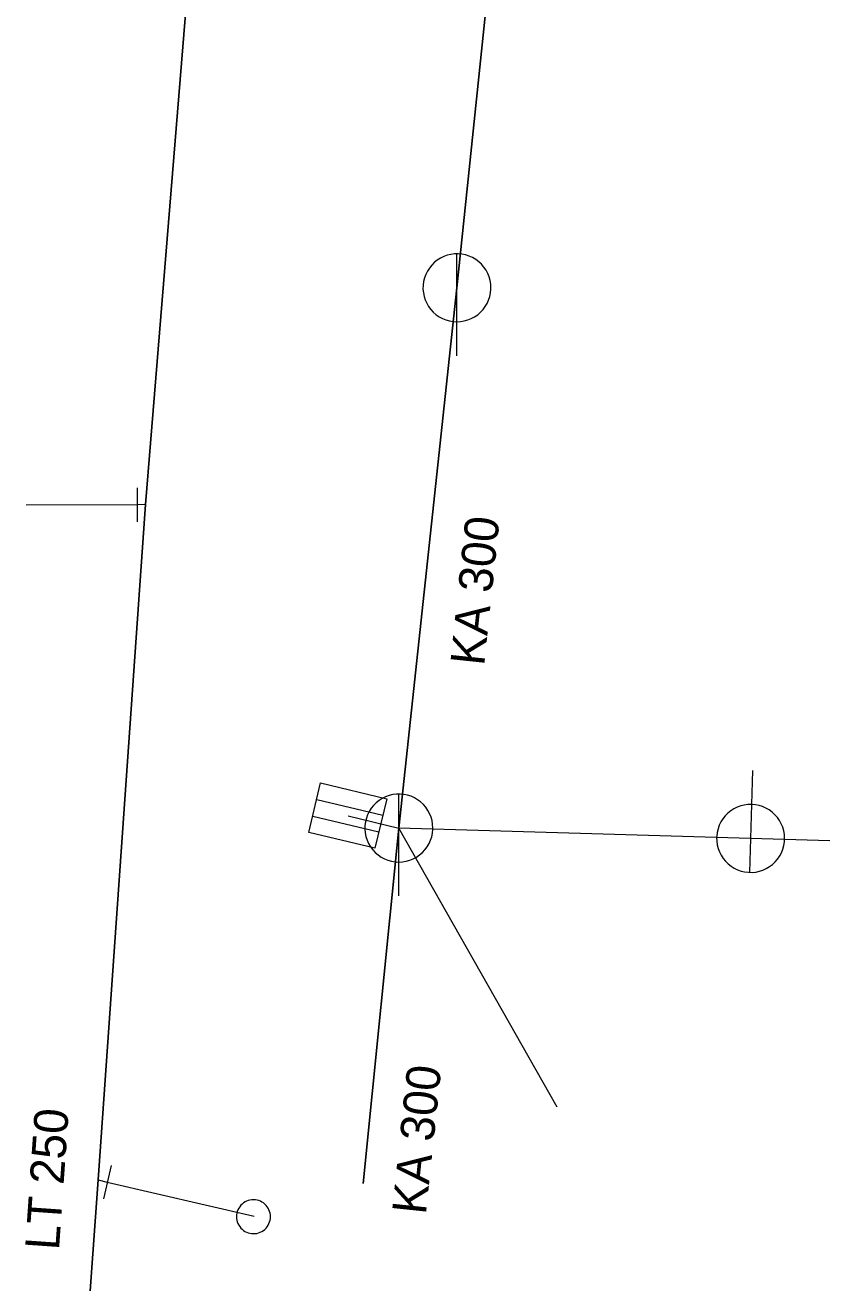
# Model space of a CAD drawing. Extents: x -783064 to -782702, y -1007904 to -1007145.
# Drawn here: x -782834.13 to -782810.46, y -1007875.4 to -1007838.15 of the extents above; entities that cross this region are included whole.
import ezdxf

# ---------------------------------------------------------------- set-up
doc = ezdxf.new("R2010")
doc.units = 0
doc.header["$LTSCALE"] = 0.4
for name, color, linetype, lineweight in [('1', 7, 'Continuous', 13), ('11', 7, 'Continuous', 13), ('13', 7, 'Continuous', 13), ('14', 7, 'Continuous', 13), ('17', 7, 'Continuous', 25), ('22', 7, 'Continuous', 13), ('23', 7, 'Continuous', 13), ('34', 7, 'Continuous', 13)]:
    doc.layers.add(name, color=color, linetype=linetype, lineweight=lineweight)

msp = doc.modelspace()

# ---------------------------------------------------------------- linework, layer by layer
at = {"layer": '11'}
for p, q in [((-782824.633, -1007861.424), (-782823.14, -1007861.78)), ((-782812.79, -1007862.087), (-782823.14, -1007861.78)), ((-782818.485, -1007869.999), (-782823.14, -1007861.78)), ((-782810.463, -1007862.158), (-782812.79, -1007862.087))]:
    msp.add_line(p, q, dxfattribs=at)
at = {"layer": '13'}
for p, q in [((-782830.827, -1007852.269), (-782834.101, -1007852.274)), ((-782831.719, -1007872.202), (-782827.392, -1007873.2))]:
    msp.add_line(p, q, dxfattribs=at)
at = {"layer": '14', "lineweight": 25}
for p, q in [((-782821.43, -1007845.88), (-782818.989, -1007822.32)), ((-782823.14, -1007861.78), (-782821.43, -1007845.88)), ((-782824.192, -1007872.242), (-782823.14, -1007861.78))]:
    msp.add_line(p, q, dxfattribs=at)
at = {"layer": '14'}
for p, q in [((-782830.594, -1007852.256), (-782830.827, -1007852.269)), ((-782831.989, -1007872.135), (-782831.719, -1007872.202))]:
    msp.add_line(p, q, dxfattribs=at)
at = {"layer": '17'}
msp.add_lwpolyline([(-782828.114, -1007821.004), (-782829.348, -1007836.974), (-782830.594, -1007852.256), (-782831.989, -1007872.135), (-782832.224, -1007875.397)], dxfattribs=at)
at = {"layer": '22'}
for p, q in [((-782821.43, -1007847.88), (-782821.429, -1007844.88)), ((-782812.73, -1007860.087), (-782812.819, -1007863.086)), ((-782825.556, -1007860.939), (-782823.611, -1007861.403)), ((-782823.14, -1007863.78), (-782823.139, -1007860.78)), ((-782825.672, -1007861.426), (-782823.727, -1007861.89))]:
    msp.add_line(p, q, dxfattribs=at)
for points in [[(-782820.43, -1007845.88), (-782820.435, -1007845.771), (-782820.453, -1007845.663), (-782820.483, -1007845.557), (-782820.523, -1007845.456), (-782820.575, -1007845.359), (-782820.637, -1007845.269), (-782820.709, -1007845.186), (-782820.789, -1007845.112), (-782820.877, -1007845.046), (-782820.971, -1007844.991), (-782821.071, -1007844.946), (-782821.176, -1007844.913), (-782821.283, -1007844.891), (-782821.392, -1007844.881), (-782821.502, -1007844.883), (-782821.61, -1007844.897), (-782821.717, -1007844.922), (-782821.82, -1007844.959), (-782821.918, -1007845.008), (-782822.01, -1007845.066), (-782822.096, -1007845.135), (-782822.173, -1007845.212), (-782822.242, -1007845.298), (-782822.301, -1007845.39), (-782822.349, -1007845.488), (-782822.386, -1007845.591), (-782822.412, -1007845.698), (-782822.426, -1007845.806), (-782822.429, -1007845.916), (-782822.419, -1007846.025), (-782822.398, -1007846.132), (-782822.364, -1007846.236), (-782822.32, -1007846.336), (-782822.265, -1007846.431), (-782822.199, -1007846.519), (-782822.125, -1007846.599), (-782822.042, -1007846.671), (-782821.952, -1007846.733), (-782821.856, -1007846.785), (-782821.754, -1007846.826), (-782821.649, -1007846.856), (-782821.541, -1007846.874), (-782821.431, -1007846.88), (-782821.322, -1007846.874), (-782821.214, -1007846.856), (-782821.109, -1007846.827), (-782821.007, -1007846.786), (-782820.91, -1007846.734), (-782820.82, -1007846.672), (-782820.737, -1007846.601), (-782820.662, -1007846.521), (-782820.597, -1007846.433), (-782820.541, -1007846.339), (-782820.497, -1007846.239), (-782820.463, -1007846.135), (-782820.441, -1007846.027), (-782820.431, -1007845.918)], [(-782825.44, -1007860.453), (-782823.495, -1007860.917), (-782823.843, -1007862.376), (-782825.788, -1007861.912)], [(-782822.14, -1007861.78), (-782822.145, -1007861.671), (-782822.163, -1007861.563), (-782822.193, -1007861.457), (-782822.233, -1007861.356), (-782822.285, -1007861.259), (-782822.347, -1007861.169), (-782822.419, -1007861.086), (-782822.499, -1007861.012), (-782822.587, -1007860.946), (-782822.681, -1007860.891), (-782822.781, -1007860.846), (-782822.886, -1007860.813), (-782822.993, -1007860.791), (-782823.102, -1007860.781), (-782823.212, -1007860.783), (-782823.32, -1007860.797), (-782823.427, -1007860.822), (-782823.53, -1007860.859), (-782823.628, -1007860.908), (-782823.72, -1007860.966), (-782823.806, -1007861.035), (-782823.883, -1007861.112), (-782823.952, -1007861.198), (-782824.011, -1007861.29), (-782824.059, -1007861.388), (-782824.096, -1007861.491), (-782824.122, -1007861.598), (-782824.136, -1007861.706), (-782824.139, -1007861.816), (-782824.129, -1007861.925), (-782824.108, -1007862.032), (-782824.074, -1007862.136), (-782824.03, -1007862.236), (-782823.975, -1007862.331), (-782823.909, -1007862.419), (-782823.835, -1007862.499), (-782823.752, -1007862.571), (-782823.662, -1007862.633), (-782823.566, -1007862.685), (-782823.464, -1007862.726), (-782823.359, -1007862.756), (-782823.251, -1007862.774), (-782823.141, -1007862.78), (-782823.032, -1007862.774), (-782822.924, -1007862.756), (-782822.819, -1007862.727), (-782822.717, -1007862.686), (-782822.62, -1007862.634), (-782822.53, -1007862.572), (-782822.447, -1007862.501), (-782822.372, -1007862.421), (-782822.307, -1007862.333), (-782822.251, -1007862.239), (-782822.207, -1007862.139), (-782822.173, -1007862.035), (-782822.151, -1007861.927), (-782822.141, -1007861.818)], [(-782813.789, -1007862.056), (-782813.786, -1007862.165), (-782813.771, -1007862.274), (-782813.745, -1007862.381), (-782813.708, -1007862.483), (-782813.659, -1007862.581), (-782813.599, -1007862.673), (-782813.53, -1007862.758), (-782813.452, -1007862.835), (-782813.366, -1007862.903), (-782813.274, -1007862.961), (-782813.175, -1007863.009), (-782813.071, -1007863.045), (-782812.965, -1007863.07), (-782812.856, -1007863.083), (-782812.746, -1007863.085), (-782812.638, -1007863.074), (-782812.53, -1007863.052), (-782812.426, -1007863.018), (-782812.327, -1007862.972), (-782812.233, -1007862.917), (-782812.145, -1007862.85), (-782812.066, -1007862.776), (-782811.994, -1007862.692), (-782811.932, -1007862.602), (-782811.882, -1007862.505), (-782811.841, -1007862.403), (-782811.812, -1007862.297), (-782811.795, -1007862.19), (-782811.79, -1007862.08), (-782811.797, -1007861.97), (-782811.814, -1007861.863), (-782811.845, -1007861.758), (-782811.886, -1007861.657), (-782811.939, -1007861.56), (-782812.002, -1007861.47), (-782812.073, -1007861.388), (-782812.154, -1007861.314), (-782812.242, -1007861.249), (-782812.337, -1007861.194), (-782812.438, -1007861.15), (-782812.542, -1007861.117), (-782812.649, -1007861.096), (-782812.759, -1007861.086), (-782812.868, -1007861.089), (-782812.976, -1007861.104), (-782813.082, -1007861.13), (-782813.185, -1007861.168), (-782813.284, -1007861.217), (-782813.376, -1007861.276), (-782813.461, -1007861.345), (-782813.538, -1007861.422), (-782813.606, -1007861.509), (-782813.664, -1007861.601), (-782813.711, -1007861.699), (-782813.748, -1007861.802), (-782813.774, -1007861.91), (-782813.787, -1007862.018)]]:
    msp.add_lwpolyline(points, close=True, dxfattribs=at)
at = {"layer": '23'}
for points in [[(-782826.92, -1007873.274), (-782826.917, -1007873.221), (-782826.919, -1007873.168), (-782826.928, -1007873.118), (-782826.941, -1007873.067), (-782826.96, -1007873.018), (-782826.984, -1007872.971), (-782827.012, -1007872.927), (-782827.045, -1007872.887), (-782827.082, -1007872.849), (-782827.122, -1007872.816), (-782827.166, -1007872.787), (-782827.213, -1007872.763), (-782827.261, -1007872.744), (-782827.311, -1007872.731), (-782827.362, -1007872.722), (-782827.416, -1007872.72), (-782827.467, -1007872.722), (-782827.52, -1007872.73), (-782827.569, -1007872.743), (-782827.619, -1007872.761), (-782827.666, -1007872.786), (-782827.71, -1007872.814), (-782827.751, -1007872.848), (-782827.789, -1007872.883), (-782827.821, -1007872.924), (-782827.849, -1007872.969), (-782827.873, -1007873.014), (-782827.892, -1007873.063), (-782827.905, -1007873.114), (-782827.914, -1007873.165), (-782827.917, -1007873.217), (-782827.915, -1007873.27), (-782827.907, -1007873.322), (-782827.894, -1007873.372), (-782827.874, -1007873.42), (-782827.851, -1007873.467), (-782827.823, -1007873.512), (-782827.79, -1007873.553), (-782827.753, -1007873.59)], [(-782827.52, -1007872.73), (-782827.569, -1007872.743), (-782827.619, -1007872.761), (-782827.666, -1007872.786), (-782827.71, -1007872.814), (-782827.751, -1007872.848), (-782827.789, -1007872.883), (-782827.821, -1007872.924), (-782827.849, -1007872.969), (-782827.873, -1007873.014), (-782827.892, -1007873.063), (-782827.905, -1007873.114), (-782827.914, -1007873.165), (-782827.917, -1007873.217), (-782827.915, -1007873.27), (-782827.907, -1007873.322), (-782827.894, -1007873.372), (-782827.874, -1007873.42), (-782827.851, -1007873.467), (-782827.823, -1007873.512), (-782827.79, -1007873.553), (-782827.753, -1007873.59), (-782827.713, -1007873.623), (-782827.668, -1007873.651), (-782827.623, -1007873.676), (-782827.573, -1007873.694), (-782827.523, -1007873.707), (-782827.472, -1007873.716), (-782827.42, -1007873.718), (-782827.367, -1007873.717), (-782827.315, -1007873.709), (-782827.265, -1007873.695), (-782827.215, -1007873.676), (-782827.169, -1007873.654), (-782827.125, -1007873.624), (-782827.084, -1007873.592), (-782827.048, -1007873.556), (-782827.013, -1007873.514), (-782826.985, -1007873.47), (-782826.961, -1007873.424)], [(-782827.753, -1007873.59), (-782827.713, -1007873.623), (-782827.668, -1007873.651), (-782827.623, -1007873.676), (-782827.573, -1007873.694), (-782827.523, -1007873.707), (-782827.472, -1007873.716), (-782827.42, -1007873.718), (-782827.367, -1007873.717), (-782827.315, -1007873.709), (-782827.265, -1007873.695), (-782827.215, -1007873.676), (-782827.169, -1007873.654), (-782827.125, -1007873.624), (-782827.084, -1007873.592), (-782827.048, -1007873.556), (-782827.013, -1007873.514), (-782826.985, -1007873.47), (-782826.961, -1007873.424), (-782826.943, -1007873.375), (-782826.929, -1007873.325), (-782826.92, -1007873.274), (-782826.917, -1007873.221), (-782826.919, -1007873.168), (-782826.928, -1007873.118), (-782826.941, -1007873.067), (-782826.96, -1007873.018), (-782826.984, -1007872.971), (-782827.012, -1007872.927), (-782827.045, -1007872.887), (-782827.082, -1007872.849), (-782827.122, -1007872.816), (-782827.166, -1007872.787), (-782827.213, -1007872.763), (-782827.261, -1007872.744), (-782827.311, -1007872.731), (-782827.362, -1007872.722), (-782827.416, -1007872.72), (-782827.467, -1007872.722), (-782827.52, -1007872.73)], [(-782826.961, -1007873.424), (-782826.943, -1007873.375), (-782826.929, -1007873.325), (-782826.92, -1007873.274)]]:
    msp.add_lwpolyline(points, dxfattribs=at)
at = {"layer": '34'}
for p, q in [((-782830.825, -1007852.768), (-782830.827, -1007851.768)), ((-782831.607, -1007871.714), (-782831.831, -1007872.689))]:
    msp.add_line(p, q, dxfattribs=at)

# ---------------------------------------------------------------- texts
at = {"layer": '1'}
for s, rotation, p in [('KA 300', 84, (-782820.631, -1007857.024)), ('KA 300', 84, (-782822.346, -1007873.177)), ('LT 250', 86, (-782833.14, -1007874.221))]:
    msp.add_text(s, height=1, rotation=rotation, dxfattribs=at).set_placement(p)

doc.saveas('drawing.dxf')
